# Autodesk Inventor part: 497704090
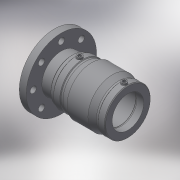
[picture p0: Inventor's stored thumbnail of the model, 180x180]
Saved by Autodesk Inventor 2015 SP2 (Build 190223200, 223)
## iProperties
Created: 2017-06
Part Number: 497704090
Material: Generic
Description: PLASSON PE CAST IRON SPIGOT COUPLER TRANSITION 225-200
Document SubType Name: Modeling
Designer: KIM
Mass: 55.0731 g
Surface Area: 148.067 cm^2
Volume: 55.0731 cm^3
Density: 1 g/cm^3
Appearance: Default
Author: KIM
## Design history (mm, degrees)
derived "497704.ipt"
feature "Solid1::497704.ipt"
tag "TaggingFeature1"
body "Solid1"
other parameters: "d13" = 148, "d14" = 17.6296, "d15" = 73, "d16" = 73, "d17" = 85.5, "d19" = 3.52592, "d20" = 168 deg, "d22" = 130.66, "d23" = 139, "d24" = 126.7402, "d25" = 135 deg, "d26" = 59.2, "d27" = 135 deg, "d35" = 15, "d39" = 5 deg, "d45" = 4, "d46" = 14, "d47" = 0, "d50" = 3, "d51" = 0, "d52" = 21.17, "d53" = 5.2925, "d55" = 0.1, "d56" = 123.71, "d58" = 68, "d60" = 67, "d62" = 4.17, "d65" = 2.78, "d68" = 139, "d71" = 6.66667, "d72" = 111.339, "d73" = 12, "d74" = 18, "d77" = 0, "d79" = 360 deg, "L_" = 216, "L_1" = 73, "D_1" = 139, "d_2" = 12, "L_2" = 68, "H_" = 109, "d_1" = 67, "S_" = 18
